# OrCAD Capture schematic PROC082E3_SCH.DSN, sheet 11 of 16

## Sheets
11 15. POWER: size C; title: POWER
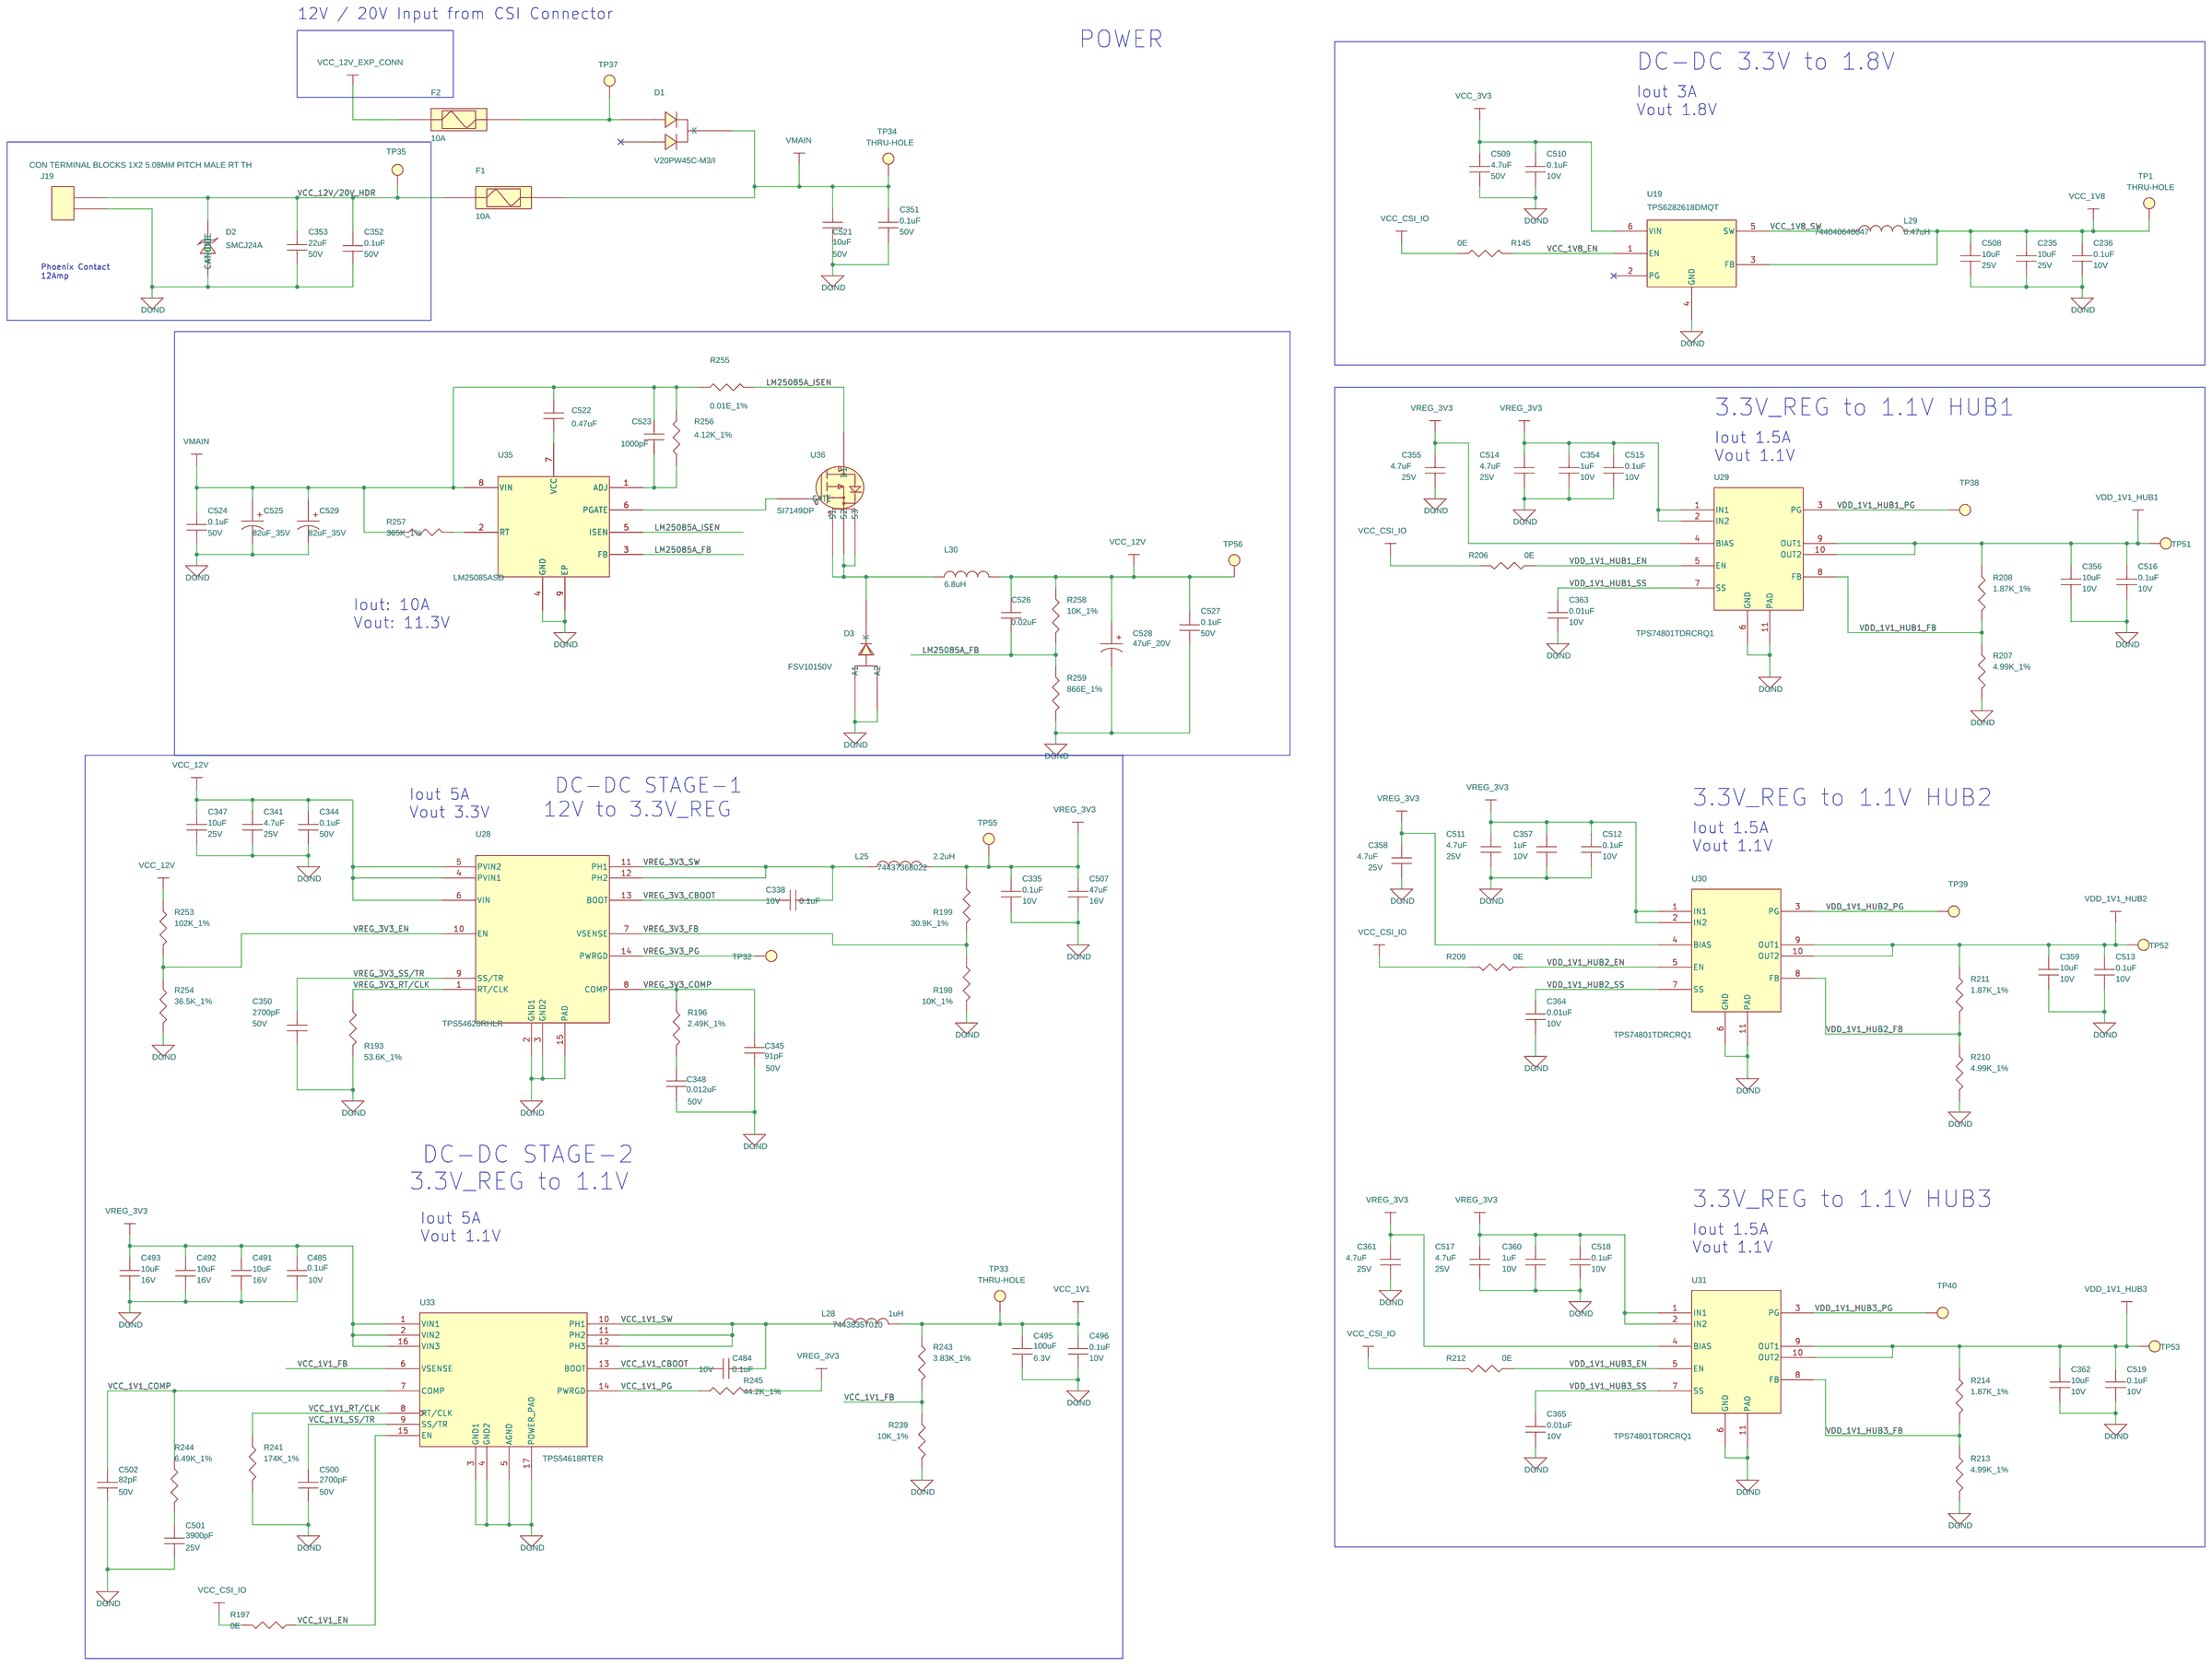
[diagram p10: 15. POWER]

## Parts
C235  10uF  [CAP0603_1]
C236  0.1uF  [CAP0402_0-75]
C335  0.1uF  [CAP0402_0-75]
C338  0.1uF  [CAP0402_0-75]
C341  4.7uF  [CAP0805_1-5]
C344  0.1uF  [CAP0402_0-75]
C345  91pF  [CAP0402_0-75]
C347  10uF  [CAP0603_1]
C348  0.012uF  [CAP0402_0-75]
C350  2700pF  [CAP0402_0-75]
C351  0.1uF  [CAP0402_0-75]
C352  0.1uF  [CAP0402_0-75]
C353  22uF  [CAP2220_5-5]
C354  1uF  [CAP0402_0-75]
C355  4.7uF  [CAP0805_1-5]
C356  10uF  [CAP0402_0-75]
C357  1uF  [CAP0402_0-75]
C358  4.7uF  [CAP0805_1-5]
C359  10uF  [CAP0402_0-75]
C360  1uF  [CAP0402_0-75]
C361  4.7uF  [CAP0805_1-5]
C362  10uF  [CAP0402_0-75]
C363  0.01uF  [CAP0201_0-5]
C364  0.01uF  [CAP0201_0-5]
C365  0.01uF  [CAP0201_0-5]
C484  0.1uF  [CAP0402_0-75]
C485  0.1uF  [CAP0402_0-75]
C491  10uF  [CAP0603_1]
C492  10uF  [CAP0603_1]
C493  10uF  [CAP0603_1]
C495  100uF  [CAP1206_2]
C496  0.1uF  [CAP0402_0-75]
C500  2700pF  [CAP0402_0-75]
C501  3900pF  [CAP0402_0-75]
C502  82pF  [CAP0402_0-75]
C507  47uF  [CAP1210_2-75]
C508  10uF  [CAP0603_1]
C509  4.7uF  [CAP1206_2]
C510  0.1uF  [CAP0402_0-75]
C511  4.7uF  [CAP0805_1-5]
C512  0.1uF  [CAP0402_0-75]
C513  0.1uF  [CAP0402_0-75]
C514  4.7uF  [CAP0805_1-5]
C515  0.1uF  [CAP0402_0-75]
C516  0.1uF  [CAP0402_0-75]
C517  4.7uF  [CAP0805_1-5]
C518  0.1uF  [CAP0402_0-75]
C519  0.1uF  [CAP0402_0-75]
C521  10uF  [CAP1206_2]
C522  0.47uF  [CAP0402_0-75]
C523  1000pF  [CAP0402_0-75]
C524  0.1uF  [CAP0402_0-75]
C525  82uF_35V  [CAPAE_E12CASE_12]
C526  0.02uF  [CAP1206_1]
C527  0.1uF  [CAP0402_0-75]
C528  47uF_20V  [CAPT6032C_3]
C529  82uF_35V  [CAPAE_E12CASE_12]
D1  V20PW45C-M3/I  [TO-252AE-3_V20PW45C_1-6]
D2  SMCJ24A  [DIO_SMC_2-7]
D3  FSV10150V  [TO277-3_FSV10150V_1-2]
F1  10A  [FUSEH_154004_380X200_SMD_3-9]
F2  10A  [FUSEH_154004_380X200_SMD_3-9]
J19  CON_TRBLK_1X2  [CON_TB1X2_1757242_P_R_T_8-6]
L25  2.2uH  [IND_74437368022_410X410_SMD_4]
L28  1uH  [IND_74438357010_170X170_SMD_3-1]
L29  0.47uH  [IND_744040640047_250X250_SMD_4-5]
L30  6.8uH  [IND_XAL1010_460X410_SMD]
R145  0E  [RES0402_0-5]
R193  53.6K_1%  [RES0402_0-5]
R196  2.49K_1%  [RES0402_0-5]
R197  0E  [RES0402_0-5]
R198  10K_1%  [RES0402_0-5]
R199  30.9K_1%  [RES0402_0-5]
R206  0E  [RES0402_0-5]
R207  4.99K_1%  [RES0402_0-5]
R208  1.87K_1%  [RES0402_0-5]
R209  0E  [RES0402_0-5]
R210  4.99K_1%  [RES0402_0-5]
R211  1.87K_1%  [RES0402_0-5]
R212  0E  [RES0402_0-5]
R213  4.99K_1%  [RES0402_0-5]
R214  1.87K_1%  [RES0402_0-5]
R239  10K_1%  [RES0402_0-5]
R241  174K_1%  [RES0402_0-5]
R243  3.83K_1%  [RES0402_0-5]
R244  6.49K_1%  [RES0402_0-5]
R245  44.2K_1%  [RES0402_0-5]
R253  102K_1%  [RES0402_0-5]
R254  36.5K_1%  [RES0402_0-5]
R255  0.01E_1%  [RES1206_0-75]
R256  4.12K_1%  [RES0402_0-5]
R257  365K_1%  [RES0402_0-5]
R258  10K_1%  [RES0201_0-5]
R259  866E_1%  [RES0402_0-5]
TP1  THRU HOLE  [TP_40X65]
TP32  TP40_SMD  [TP40_SMD]
TP33  THRU HOLE  [TP_40X65]
TP34  THRU HOLE  [TP_40X65]
TP35  TP40_SMD  [TP40_SMD]
TP37  TP40_SMD  [TP40_SMD]
TP38  TP30_SMD  [TP30_SMD]
TP39  TP30_SMD  [TP30_SMD]
TP40  TP30_SMD  [TP30_SMD]
TP51  TP40_SMD  [TP40_SMD]
TP52  TP40_SMD  [TP40_SMD]
TP53  TP40_SMD  [TP40_SMD]
TP55  TP40_SMD  [TP40_SMD]
TP56  TP40_SMD  [TP40_SMD]
U19  TPS6282618DMQT  [VSONHR6_TPS62826_60X60_1]
U28  TPS54620RHLR  [QFN14_19-68_145X145]
U29  TPS74801TDRCRQ1  [VSON10_TPS74801-Q1_120X120_1]
U30  TPS74801TDRCRQ1  [VSON10_TPS74801-Q1_120X120_1]
U31  TPS74801TDRCRQ1  [VSON10_TPS74801-Q1_120X120_1]
U33  TPS54618RTER  [QFN16_19-68_120X120_0-8_EP1-8]
U35  LM25085ASD  [DFN8_19-68_120X120_0-8_EP1-7X2-1]
U36  SI7149DP  [POWERPAKSO8_SI7848BDP_240X200_1-2]

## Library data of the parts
C235 C508 = CAP: CAP CERAMIC 10uF 25V 20% X5R 0603; Chkd/date: MANIRAJA/130617; Crtd /date: MUDDU/130810; Custom_Duty: 15%; Customs_HS_Code: 85322990; Distributor_name: DIGIKEY; Distributor_part_number: 490-7202-1-ND; Footprint Path: Y:\MIS_DATABASE\Library\ALTIUM_TOOL\PCB_FOOTPRINTS\Altium_Footprint_Lib.PcbLib; Height: 0.90MM; Library Path: Y:\MIS_DATABASE\Library\ALTIUM_TOOL\SCHEMATICS_PARTS\MS_DISCRETE_Library.schlib; Mfr_name: MURATA; Mfr_part_number: GRM188R61E106MA73D; Mistral Part No: 120013060015-R; Package: 0603; Part_type: CAPACITORS\CERAMIC; Project: PB_BUGBASE; RoHS: RoHS; Temperature: -55°C+85°C; Tolerance: 20%; Voltage: 25V; Wattage: NA; Weight: 6.3mg; Datasheet: Y:\MIS_DATABASE\DATASHEETS\CAPACITORS\MURATA-GXX-SER_NOV17.PDF
C236 C335 C338 C484 C485 C496 C510 C512 C513 C515 C516 C518 C519 = CAP: CAP CERAMIC 0.1uF 10V 10% X7R 0402; Automotive Alternate_mfr_name: TDK; Automotive Alternate_mfr_part_number: CGA2B1X7R1C104K050BC; Chkd/date: MANIRAJA/190218; Crtd /date: ALVY/160218; Custom_Duty: 15%; Customs_HS_Code: 85322990; Direct Alternate_mfr_name: TDK; Direct Alternate_mfr_part_number: CGA2B1X7R1C104K050BC; Distributor_name: DIGIKEY; Distributor_part_number: 490-6321-1-ND; Footprint Path: Y:\MIS_DATABASE\Library\ALTIUM_TOOL\PCB_FOOTPRINTS\Altium_Footprint_Lib.PcbLib; Height: 0.55MM; Library Path: Y:\MIS_DATABASE\Library\ALTIUM_TOOL\SCHEMATICS_PARTS\MS_DISCRETE_Library.schlib; Mfr_name: MURATA; Mfr_part_number: GRM155R71A104KA01D; Mistral Part No: 120018020011-R; Package: 0402; Part_type: CAPACITORS\CERAMIC; Project: GRACO SMART MODULE; RoHS: RoHS; Temperature: -55°C+125°C; Tolerance: 10%; Voltage: 10V; Wattage: NA; Weight: 6mg; Datasheet: Y:\MIS_DATABASE\DATASHEETS\CAPACITORS\GRM155R71A104KA01D.PDF
C341 = CAP: CAP CERAMIC 4.7uF 25V 10% X7R 0805; Chkd/date: MANIRAJA/301120; Crtd /date: ALVY/301120; Custom_Duty: 15%; Customs_HS_Code: 85322990; Distributor_name: MOUSER; Distributor_part_number: 81-GRM21BZ71E475KE5L; Footprint Path: Y:\MIS_DATABASE\Library\ALTIUM_TOOL\PCB_FOOTPRINTS\Altium_Footprint_Lib.PcbLib; Height: 1.45MM; Library Path: Y:\MIS_DATABASE\Library\ALTIUM_TOOL\SCHEMATICS_PARTS\MS_DISCRETE_Library.schlib; Mfr_name: MURATA; Mfr_part_number: GRM21BZ71E475KE15L; Mistral Part No: 120014060005-R; Package: 0805; Part_type: CAPACITORS\CERAMIC; Project: TI_J7ES_EVM_FUSION2_SER_CAP; RoHS: RoHS; Temperature: -55°C+125°C; Tolerance: 10%; Voltage: 25V; Wattage: NA; Weight: 1.6mg; Datasheet: Y:\MIS_DATABASE\DATASHEETS\CAPACITORS\GRM21BZ71E475KE15.PDF
C344 C351 C352 C524 C527 = CAP: CAP CERAMIC 0.1uF 50V 10% X7R 0402; Chkd/date: MANIRAJA/131217; Crtd /date: ALVY/131217; Custom_Duty: 15%; Customs_HS_Code: 85322990; Distributor_name: DIGIKEY; Distributor_part_number: 478-10043-1-ND; Footprint Path: Y:\MIS_DATABASE\Library\ALTIUM_TOOL\PCB_FOOTPRINTS\Altium_Footprint_Lib.PcbLib; Height: 0.56MM; Library Path: Y:\MIS_DATABASE\Library\ALTIUM_TOOL\SCHEMATICS_PARTS\MS_DISCRETE_Library.schlib; Mfr_name: AVX CORPORATION; Mfr_part_number: 04025C104KAT2A; Mistral Part No: 120011100014-R; Package: 0402; Part_type: CAPACITORS\CERAMIC; Project: ASL_LIU_TYPE-II; RoHS: RoHS; Temperature: -55°C+125°C; Tolerance: 10%; Voltage: 50V; Wattage: NA; Weight: 0.65mg; Datasheet: Y:\MIS_DATABASE\DATASHEETS\CAPACITORS\AVX_MLC.PDF
C345 = CAP: CAP CERAMIC 91pF 50V 5% C0G(NP0) 0402; Chkd/date: VASANTHA/100215; Crtd /date: USMAN/170513; Custom_Duty: 15%; Customs_HS_Code: 85322990; Distributor_name: DIGIKEY; Distributor_part_number: 490-5954-1-ND; Footprint Path: Y:\MIS_DATABASE\Library\ALTIUM_TOOL\PCB_FOOTPRINTS\Altium_Footprint_Lib.PcbLib; Height: 0.55MM; Library Path: Y:\MIS_DATABASE\Library\ALTIUM_TOOL\SCHEMATICS_PARTS\MS_DISCRETE_Library.schlib; Mfr_name: MURATA; Mfr_part_number: GRM1555C1H910JA01D; Mistral Part No: 120013050007-R; Package: 0402; Part_type: CAPACITORS\CERAMIC; Project: DTRM; RoHS: RoHS; Temperature: -55°C+125°C; Tolerance: 5%; Voltage: 50V; Wattage: NA; Weight: 6mg; Datasheet: Y:\MIS_DATABASE\DATASHEETS\CAPACITORS\MURATA-GXX-SER_NOV17.PDF
C347 = CAP: CAP CERAMIC 10uF 25V 20% X5R 0603; Automotive Alternate_mfr_name: MURATA; Automotive Alternate_mfr_part_number: GRT188R61E106ME13D; Chkd/date: MANIRAJA/130617; Crtd /date: MUDDU/130810; Custom_Duty: 15%; Customs_HS_Code: 85322990; Direct Alternate_mfr_name: TDK; Direct Alternate_mfr_part_number: C1608X5R1E106M080AC; Distributor_name: DIGIKEY; Distributor_part_number: 490-7202-1-ND; Footprint Path: Y:\MIS_DATABASE\Library\ALTIUM_TOOL\PCB_FOOTPRINTS\Altium_Footprint_Lib.PcbLib; Height: 0.90MM; Library Path: Y:\MIS_DATABASE\Library\ALTIUM_TOOL\SCHEMATICS_PARTS\MS_DISCRETE_Library.schlib; Mfr_name: MURATA; Mfr_part_number: GRM188R61E106MA73D; Mistral Part No: 120013060015-R; Package: 0603; Part_type: CAPACITORS\CERAMIC; Project: PB_BUGBASE; RoHS: RoHS; Temperature: -55°C+85°C; Tolerance: 20%; Voltage: 25V; Wattage: NA; Weight: 6.3mg; Datasheet: Y:\MIS_DATABASE\DATASHEETS\CAPACITORS\MURATA-GXX-SER_NOV17.PDF
C348 = CAP: CAP CERAMIC 0.012uF 50V 10% X7R 0402; Chkd/date: MANIRAJA/140219; Crtd /date: ALVY/140219; Custom_Duty: 15%; Customs_HS_Code: 85322990; Distributor_name: DIGIKEY; Distributor_part_number: 1292-1182-1-ND; Footprint Path: Y:\MIS_DATABASE\Library\ALTIUM_TOOL\PCB_FOOTPRINTS\Altium_Footprint_Lib.PcbLib; Height: 0.70MM; Library Path: Y:\MIS_DATABASE\Library\ALTIUM_TOOL\SCHEMATICS_PARTS\MS_DISCRETE_Library.schlib; Mfr_name: WALSIN TECHNOLOGY; Mfr_part_number: 0402B123K500CT; Mistral Part No: 120019020007-R; Package: 0402; Part_type: CAPACITORS\CERAMIC; Project: GRACO SMART MODULE; RoHS: RoHS; Temperature: -55°C+125°C; Tolerance: 10%; Voltage: 50V; Wattage: NA; Weight: NA; Datasheet: Y:\MIS_DATABASE\DATASHEETS\CAPACITORS\0402B123K500CT.PDF
C350 C500 = CAP: CAP CERAMIC 2700pF 50V 10% X7R 0402; Chkd/date: VASANTHA/201216; Crtd /date: CHAITHANYA/071111; Custom_Duty: 15%; Customs_HS_Code: 85322990; Distributor_name: DIGIKEY; Distributor_part_number: 490-1306-1-ND; Footprint Path: Y:\MIS_DATABASE\Library\ALTIUM_TOOL\PCB_FOOTPRINTS\Altium_Footprint_Lib.PcbLib; Height: 0.55MM; Library Path: Y:\MIS_DATABASE\Library\ALTIUM_TOOL\SCHEMATICS_PARTS\MS_DISCRETE_Library.schlib; Mfr_name: MURATA; Mfr_part_number: GRM155R71H272KA01D; Mistral Part No: 120011110004-R; Package: 0402; Part_type: CAPACITORS\CERAMIC; Project: DLRL_FPGA_DEV_PF; RoHS: RoHS; Temperature: -55°C+125°C; Tolerance: 10%; Voltage: 50V; Wattage: NA; Weight: 6mg; Datasheet: Y:\MIS_DATABASE\DATASHEETS\CAPACITORS\GRM155R71H272KA01.PDF
C353 = CAP: CAP CERAMIC 22uF 50V 20% X5R 2220; Chkd/date: BAVISH/081111; Crtd /date: CHAITHANYA/211011; Custom_Duty: 15%; Customs_HS_Code: 85322990; Distributor_name: DIGIKEY; Distributor_part_number: 445-1655-1-ND; Footprint Path: Y:\MIS_DATABASE\Library\ALTIUM_TOOL\PCB_FOOTPRINTS\Altium_Footprint_Lib.PcbLib; Height: 5.50MM; Library Path: Y:\MIS_DATABASE\Library\ALTIUM_TOOL\SCHEMATICS_PARTS\MS_DISCRETE_Library.schlib; Mfr_name: TDK CORPORATION; Mfr_part_number: CKG57NX5R1H226M500JH; Mistral Part No: 120011100042-R; Package: 2220; Part_type: CAPACITORS\CERAMIC; Project: NA10NG; RoHS: RoHS; Temperature: -55°C+85°C; Tolerance: 20%; Voltage: 50V; Wattage: NA; Weight: NA; Datasheet: Y:\MIS_DATABASE\DATASHEETS\CAPACITORS\CKG57NX5R1H226M500JH.PDF
C354 C357 C360 = CAP: CAP CERAMIC 1uF 10V 10% X7S AUTO 0402; Chkd/date: MANIRAJA/100918; Crtd /date: ALVY/100918; Custom_Duty: 15%; Customs_HS_Code: 85322990; Distributor_name: DIGIKEY; Distributor_part_number: 490-13409-1-ND; Footprint Path: Y:\MIS_DATABASE\Library\ALTIUM_TOOL\PCB_FOOTPRINTS\Altium_Footprint_Lib.PcbLib; Footprint Ref: CAP0402_0-5; Height: 0.70MM; Library Path: Y:\MIS_DATABASE\Library\ALTIUM_TOOL\SCHEMATICS_PARTS\MS_DISCRETE_Library.schlib; Mfr_name: MURATA; Mfr_part_number: GCM155C71A105KE38D; Mistral Part No: 120018090021-R; Package: 0402; Part_type: CAPACITORS\CERAMIC; Project: SMART-M_SCRIPTALK_PB; RoHS: RoHS; Temperature: -55°C+125°C; Tolerance: 10%; Voltage: 10V; Wattage: NA; Weight: 6mg; Datasheet: Y:\MIS_DATABASE\DATASHEETS\CAPACITORS\MURATA-GCM-SER.PDF
C355 C358 C361 C511 C514 C517 = CAP: CAP CERAMIC 4.7uF 25V 10% X5R 0805; Chkd/date: MANIRAJA/100419; Crtd /date: ALVY/100419; Custom_Duty: 15%; Customs_HS_Code: 85322990; Distributor_name: DIGIKEY; Distributor_part_number: 399-5505-1-ND; Footprint Path: Y:\MIS_DATABASE\Library\ALTIUM_TOOL\PCB_FOOTPRINTS\Altium_Footprint_Lib.PcbLib; Height: 1.40MM; Library Path: Y:\MIS_DATABASE\Library\ALTIUM_TOOL\SCHEMATICS_PARTS\MS_DISCRETE_Library.schlib; Mfr_name: KEMET; Mfr_part_number: C0805C475K3PACTU; Mistral Part No: 120011020009-R; Package: 0805; Part_type: CAPACITORS\CERAMIC; Project: S-BAND_TM-2W_PS; RoHS: RoHS; Temperature: -55°C+85°C; Tolerance: 10%; Voltage: 25V; Wattage: NA; Weight: 5.5mg; Datasheet: Y:\MIS_DATABASE\DATASHEETS\CAPACITORS\KEMET-C-X5R.PDF
C356 C359 C362 = CAP: CAP CERAMIC 10uF 10V 20% X5R 0402; Chkd/date: VASANTHA/291216; Crtd /date: USMAN/261113; Custom_Duty: 15%; Customs_HS_Code: 85322990; Distributor_name: DIGIKEY; Distributor_part_number: 1276-1450-1-ND; Footprint Path: Y:\MIS_DATABASE\Library\ALTIUM_TOOL\PCB_FOOTPRINTS\Altium_Footprint_Lib.PcbLib; Height: 0.55MM; Library Path: Y:\MIS_DATABASE\Library\ALTIUM_TOOL\SCHEMATICS_PARTS\MS_DISCRETE_Library.schlib; Mfr_name: SAMSUNG; Mfr_part_number: CL05A106MP5NUNC; Mistral Part No: 120013110019-R; Package: 0402; Part_type: CAPACITORS\CERAMIC; Project: C-BAND_SYNTH; RoHS: RoHS; Temperature: -55°C+85°C; Tolerance: 20%; Voltage: 10V; Wattage: NA; Weight: 0.65mg; Datasheet: Y:\MIS_DATABASE\DATASHEETS\CAPACITORS\CL05A106MP5NUNC.PDF
C363-C365 = CAP: CAP CERAMIC 0.01uF 10V 10% X5R 0201; Chkd/date: VASANTHA/270117; Crtd /date: MAZHAR/090909; Custom_Duty: 15%; Customs_HS_Code: 85322990; Distributor_name: DIGIKEY; Distributor_part_number: 490-3166-1-ND; Footprint Path: Y:\MIS_DATABASE\Library\ALTIUM_TOOL\PCB_FOOTPRINTS\Altium_Footprint_Lib.PcbLib; Footprint Ref: CAP0402_0-75; Height: 0.33MM; Library Path: Y:\MIS_DATABASE\Library\ALTIUM_TOOL\SCHEMATICS_PARTS\MS_DISCRETE_Library.schlib; Mfr_name: MURATA; Mfr_part_number: GRM033R61A103KA01D; Mistral Part No: 120011010015-R; Package: 0201; Part_type: CAPACITORS\CERAMIC; Project: VMEFMCD; RoHS: RoHS; Temperature: -55°C+85°C; Tolerance: 10%; Voltage: 10V; Wattage: NA; Weight: 0.33mg; Datasheet: Y:\MIS_DATABASE\DATASHEETS\CAPACITORS\MURATA-GXX-SER_NOV17.PDF
C491-C493 = CAP: CAP CERAMIC 10uF 16V 20% X6S 0603; Chkd/date: VASANTHA/170117; Crtd /date: VASANTHA/170117; Custom_Duty: 15%; Customs_HS_Code: 85322990; Direct Alternate_mfr_name: SAMSUNG; Direct Alternate_mfr_part_number: CL10X106MO8NRNC; Distributor_name: DIGIKEY; Distributor_part_number: 490-7198-1-ND; Height: 0.90MM; Mfr_name: MURATA; Mfr_part_number: GRM188C81C106MA73D; Mistral Part No: 120017010004-R; Package: 0603; Part_type: CAPACITORS\CERAMIC; Project: TRMM_SMART-M_PS; RoHS: RoHS; Temperature: -55°C+105°C; Tolerance: 20%; Voltage: 16V; Wattage: NA; Weight: 6.3mg; Datasheet: Y:\MIS_DATABASE\DATASHEETS\CAPACITORS\MURATA-GXX-SER_NOV17.PDF
C495 = CAP: CAP CERAMIC 100uF 6.3V 20% X5R 1206; Chkd/date: MANIRAJA/010419; Crtd /date: MANIRAJA/010419; Custom_Duty: 15%; Customs_HS_Code: 85322990; Distributor_name: DIGIKEY; Distributor_part_number: 490-7217-1-ND; Height: 1.90MM; Mfr_name: MURATA; Mfr_part_number: GRM31CR60J107ME39K; Mistral Part No: 120009030174-R; Package: 1206; Part_type: CAPACITORS\CERAMIC; Project: HS100RD; RoHS: RoHS; Temperature: -55°C+85°C; Tolerance: 20%; Voltage: 6.3V; Wattage: NA; Weight: 16.2mg; Datasheet: Y:\MIS_DATABASE\DATASHEETS\CAPACITORS\GRM31CR60J107ME39.PDF
C501 = CAP: CAP CERAMIC 3900pF 25V 5% X7R 0402; Chkd/date: MANIRAJA/061218; Crtd /date: ALVY/061218; Custom_Duty: 15%; Customs_HS_Code: 85322990; Distributor_name: DIGIKEY; Distributor_part_number: 478-11747-1-ND; Footprint Path: Y:\MIS_DATABASE\Library\ALTIUM_TOOL\PCB_FOOTPRINTS\Altium_Footprint_Lib.PcbLib; Height: 0.56MM; Library Path: Y:\MIS_DATABASE\Library\ALTIUM_TOOL\SCHEMATICS_PARTS\MS_DISCRETE_Library.schlib; Mfr_name: AVX CORPORATION; Mfr_part_number: 04023C392JAT2A; Mistral Part No: 120018120005-R; Package: 0402; Part_type: CAPACITORS\CERAMIC; Project: RFSU_POC-CARD; RoHS: RoHS; Temperature: -55°C+125°C; Tolerance: 5%; Voltage: 25V; Wattage: NA; Weight: 0.65mg; Datasheet: Y:\MIS_DATABASE\DATASHEETS\CAPACITORS\AVX_MLC.PDF
C502 = CAP: CAP CERAMIC 82pF 50V 2% C0G(NP0) 0402; Chkd/date: MANIRAJA/040620; Crtd /date: ALVY/040620; Custom_Duty: 15%; Customs_HS_Code: 85322990; Distributor_name: DIGIKEY; Distributor_part_number: 490-8229-1-ND; Footprint Path: Y:\MIS_DATABASE\Library\ALTIUM_TOOL\PCB_FOOTPRINTS\Altium_Footprint_Lib.PcbLib; Height: 0.55MM; Library Path: Y:\MIS_DATABASE\Library\ALTIUM_TOOL\SCHEMATICS_PARTS\MS_DISCRETE_Library.schlib; Mfr_name: MURATA; Mfr_part_number: GRM1555C1H820GA01D; Mistral Part No: 120020060013-R; Package: 0402; Part_type: CAPACITORS\CERAMIC; Project: MCX_80MHz_ADC_DRIVER; RoHS: RoHS; Temperature: -55°C+125°C; Tolerance: 2%; Voltage: 50V; Wattage: NA; Weight: 6mg; Datasheet: Y:\MIS_DATABASE\DATASHEETS\CAPACITORS\GRM1555C1H820GA01.PDF
C507 = CAP: CAP CERAMIC 47uF 16V 10% X6S AUTO 1210; Chkd/date: MANIRAJA/270218; Crtd /date: ALVY/260218; Custom_Duty: 15%; Customs_HS_Code: 85322990; Distributor_name: DIGIKEY; Distributor_part_number: 490-12494-1-ND; Footprint Path: Y:\MIS_DATABASE\Library\ALTIUM_TOOL\PCB_FOOTPRINTS\Altium_Footprint_Lib.PcbLib; Height: 2.70MM; Library Path: Y:\MIS_DATABASE\Library\ALTIUM_TOOL\SCHEMATICS_PARTS\MS_DISCRETE_Library.schlib; Mfr_name: MURATA; Mfr_part_number: GRT32EC81C476KE13L; Mistral Part No: 120018020017-R; Package: 1210; Part_type: CAPACITORS\CERAMIC; Project: RSAPR_TYPE-II_DIO; RoHS: RoHS; Temperature: -55°C+105°C; Tolerance: 10%; Voltage: 16V; Wattage: NA; Weight: 16mg; Datasheet: Y:\MIS_DATABASE\DATASHEETS\CAPACITORS\GRT32EC81C476KE13.PDF
C509 = CAP: CAP CERAMIC 4.7uF 50V 10% X7R 1206; Chkd/date: VASANTHA/100315; Crtd /date: NAVEED/240714; Custom_Duty: 15%; Customs_HS_Code: 85322990; Distributor_name: DIGIKEY; Distributor_part_number: 587-2994-1-ND; Footprint Path: Y:\MIS_DATABASE\Library\ALTIUM_TOOL\PCB_FOOTPRINTS\Altium_Footprint_Lib.PcbLib; Height: 1.80MM; Library Path: Y:\MIS_DATABASE\Library\ALTIUM_TOOL\SCHEMATICS_PARTS\MS_DISCRETE_Library.schlib; Mfr_name: TAIYO YUDEN; Mfr_part_number: UMK316AB7475KL-T; Mistral Part No: 120014070019-R; Package: 1206; Part_type: CAPACITORS\CERAMIC; Project: MS_ADE_PSM_PSU; RoHS: RoHS; Temperature: -55°C+125°C; Tolerance: 10%; Voltage: 50V; Wattage: NA; Weight: 16.2mg; Datasheet: Y:\MIS_DATABASE\DATASHEETS\CAPACITORS\UMK316AB7475KL-T.PDF
C521 = CAP: CAP CERAMIC 10uF 50V 10% X5R AUTO 1206; Chkd/date: MANIRAJA/261018; Crtd /date: ALVY/261018; Custom_Duty: 15%; Customs_HS_Code: 85322990; Distributor_name: DIGIKEY; Distributor_part_number: 490-12456-1-ND; Footprint Path: Y:\MIS_DATABASE\Library\ALTIUM_TOOL\PCB_FOOTPRINTS\Altium_Footprint_Lib.PcbLib; Height: 1.80MM; Library Path: Y:\MIS_DATABASE\Library\ALTIUM_TOOL\SCHEMATICS_PARTS\MS_DISCRETE_Library.schlib; Mfr_name: MURATA; Mfr_part_number: GRT31CR61H106KE01L; Mistral Part No: 120011060019-R; Package: 1206; Part_type: CAPACITORS\CERAMIC; Project: LRDE_ABCMV2_MB; RoHS: RoHS; Temperature: -55°C+85°C; Tolerance: 10%; Voltage: 50V; Wattage: NA; Weight: 16.2mg; Datasheet: Y:\MIS_DATABASE\DATASHEETS\CAPACITORS\GRT31CR61H106KE01L.PDF
C522 = CAP: CAP CERAMIC 0.47uF 50V 10% X5R 0402; Chkd/date: MANIRAJA/250821; Crtd /date: ALVY/250821; Custom_Duty: 15%; Customs_HS_Code: 85322990; Distributor_name: DIGIKEY; Distributor_part_number: 490-16354-1-ND; Footprint Path: Y:\MIS_DATABASE\Library\ALTIUM_TOOL\PCB_FOOTPRINTS\Altium_Footprint_Lib.PcbLib; Height: 0.60MM; Library Path: Y:\MIS_DATABASE\Library\ALTIUM_TOOL\SCHEMATICS_PARTS\MS_DISCRETE_Library.schlib; Mfr_name: MURATA; Mfr_part_number: GRM155R61H474KE11D; Mistral Part No: 120019050024-R; Package: 0402; Part_type: CAPACITORS\CERAMIC; Project: TI_AM335x SK_BRD; RoHS: RoHS; Temperature: -55°C+85°C; Tolerance: 10%; Voltage: 50V; Wattage: NA; Weight: 1.5mg; Datasheet: Y:\MIS_DATABASE\DATASHEETS\CAPACITORS\GRM155R61H474KE11.PDF
C523 = CAP: CAP CERAMIC 1000pF 50V 5% X7R 0402; Chkd/date: MANIRAJA/010419; Crtd /date: MANIRAJA/010419; Custom_Duty: 15%; Customs_HS_Code: 85322990; Distributor_name: DIGIKEY; Distributor_part_number: 490-6349-1-ND; Footprint Path: Y:\MIS_DATABASE\Library\ALTIUM_TOOL\PCB_FOOTPRINTS\Altium_Footprint_Lib.PcbLib; Height: 0.55MM; Library Path: Y:\MIS_DATABASE\Library\ALTIUM_TOOL\SCHEMATICS_PARTS\MS_DISCRETE_Library.schlib; Mfr_name: MURATA; Mfr_part_number: GRM155R71H102JA01J; Mistral Part No: 120013100001-R; Package: 0402; Part_type: CAPACITORS\CERAMIC; Project: C-BAND_SYNTH; RoHS: RoHS; Temperature: -55°C+125°C; Tolerance: 5%; Voltage: 50V; Wattage: NA; Weight: 6mg; Datasheet: Y:\MIS_DATABASE\DATASHEETS\CAPACITORS\GRM155R71H102JA01J.PDF
C525 C529 = CAP_POL: CAP POLYMER 82uF 35V 20% E12CASE_8383; Chkd/date: JEBRAN/250416; Crtd /date: VASANTHA/210416; Custom_Duty: 15%; Customs_HS_Code: 85322990; Distributor_name: DIGIKEY; Distributor_part_number: P16562CT-ND; Footprint Path: Y:\MIS_DATABASE\Library\ALTIUM_TOOL\PCB_FOOTPRINTS\Altium_Footprint_Lib.PcbLib; Height: 12.00MM; Library Path: Y:\MIS_DATABASE\Library\ALTIUM_TOOL\SCHEMATICS_PARTS\MS_DISCRETE_Library.schlib; Mfr_name: PANASONIC-ECG; Mfr_part_number: 35SVPF82M; Mistral Part No: 120016040007-R; Package: E12CASE_8383; Part_type: CAPACITORS\POLYPROPYLENE; Project: RCI_DLS_CARD_PS; RoHS: RoHS; Temperature: -55°C+105°C; Tolerance: 20%; Voltage: 35V; Wattage: NA; Weight: NA; Datasheet: Y:\MIS_DATABASE\DATASHEETS\CAPACITORS\SVPF-SERIES.PDF
C526 = CAP: CAP CERAMIC 0.02uF 50V 5% C0G(NP0) 1206; Chkd/date: PRAVEEN/250822; Crtd /date: PRAVEEN/250822; Custom_Duty: 15%; Customs_HS_Code: 85322990; Distributor_name: DIGIKEY; Distributor_part_number: 490-1760-1-ND; Footprint Path: Y:\MIS_DATABASE\Library\ALTIUM_TOOL\PCB_FOOTPRINTS\Altium_Footprint_Lib.PcbLib; Height: 0.95MM; Library Path: Y:\MIS_DATABASE\Library\ALTIUM_TOOL\SCHEMATICS_PARTS\MS_DISCRETE_Library.schlib; Mfr_name: MURATA; Mfr_part_number: GRM3195C1H203JA01D; Mistral Part No: 120022080076-R; Package: 1206; Part_type: CAPACITORS\CERAMIC; Project: J7ES_EVM_FUSION2_BRD; RoHS: RoHS; Temperature: -55°C+125°C; Tolerance: 5%; Voltage: 50V; Wattage: NA; Weight: 19mg; Datasheet: Y:\MIS_DATABASE\DATASHEETS\CAPACITORS\GRM3195C1H203JA01D.PDF
C528 = CAP_POL: CAP TANTALUM 47uF 20V 20% ESR 0.5E C6032; Chkd/date: ALVY/290621; Crtd /date: MANIRAJA/290621; Custom_Duty: 15%; Customs_HS_Code: 85322990; Distributor_name: DIGIKEY; Distributor_part_number: 478-8904-1-ND; Footprint Path: Y:\MIS_DATABASE\Library\ALTIUM_TOOL\PCB_FOOTPRINTS\Altium_Footprint_Lib.PcbLib; Height: 2.80MM; Library Path: Y:\MIS_DATABASE\Library\ALTIUM_TOOL\SCHEMATICS_PARTS\MS_DISCRETE_Library.schlib; Mfr_name: AVX CORPORATION; Mfr_part_number: TAJC476M020RNJ; Mistral Part No: 120021060023-R; Package: C6032; Part_type: CAPACITORS\TANTALUM; Project: MSU_BRD; RoHS: RoHS; Temperature: -55°C+125°C; Tolerance: 20%; Voltage: 20V; Wattage: NA; Weight: 300mg; Datasheet: Y:\MIS_DATABASE\DATASHEETS\CAPACITORS\AVX-TAJ-SER_OCT20.PDF
D1 = DIODE_V20PW45C: DIODE SCHOTTKY TMBS RECTIFIER 45V 10A TO-252AE-3; Chkd/date: MANIRAJA/190419; Crtd /date: MANIRAJA/190419; Custom_Duty: 15%; Customs_HS_Code: 85412900; Distributor_name: DIGIKEY; Distributor_part_number: V20PW45C-M3/IGICT-ND; Footprint Path: Y:\MIS_DATABASE\Library\ALTIUM_TOOL\PCB_FOOTPRINTS\Altium_Footprint_Lib.PcbLib; Height: 1.60MM; Library Path: Y:\MIS_DATABASE\Library\ALTIUM_TOOL\SCHEMATICS_PARTS\MS_DISCRETE_Library.schlib; Mfr_name: VISHAY; Mistral Part No: 130019040014-R; Package: TO-252AE-3; Part_type: DIODE\SCHOTTKY; Project: TI_J7ES_EVM_FUSION2_SER_CAP; RoHS: RoHS; Temperature: -40°C+150°C; Tolerance: NA; Voltage: NA; Wattage: NA; Weight: NA; Datasheet: Y:\MIS_DATABASE\DATASHEETS\DISCRETES\DIODES\V20PW45C.PDF
D2 = DIODE_TVS: DIODE TVS UNIDIR 1500W 24V SMC; Chkd/date: VASANTHA/291216; Crtd /date: MANIRAJA/281216; Custom_Duty: 15%; Customs_HS_Code: 85412900; Distributor_name: DIGIKEY; Distributor_part_number: SMCJ24ALFCT-ND; Height: 2.65MM; Mfr_name: LITTELFULE; Mistral Part No: 130016120055-R; Package: SMC; Part_type: DIODE\TVS; Project: DARE_ODM; RoHS: RoHS; Temperature: -55°C+150°C; Tolerance: NA; Voltage: 24V; Wattage: 1500W; Weight: 300mg; Datasheet: Y:\MIS_DATABASE\DATASHEETS\DISCRETES\DIODES\SMCJ-FAIRCHILD.PDF
D3 = DIODE_SCHOTTKY_SS3P4L: DIODE SCHOTTKY RECTIFIER 150V 10A TO277-3; Chkd/date: MANIRAJA/280918; Crtd /date: ALVY/280918; Custom_Duty: 15%; Customs_HS_Code: 85412900; Distributor_name: DIGIKEY; Distributor_part_number: FSV10150VCT-ND; Footprint Path: Y:\MIS_DATABASE\Library\ALTIUM_TOOL\PCB_FOOTPRINTS\Altium_Footprint_Lib.PcbLib; Height: 1.20MM; Library Path: Y:\MIS_DATABASE\Library\ALTIUM_TOOL\SCHEMATICS_PARTS\MS_DISCRETE_Library.schlib; Mfr_name: ON SEMICONDUCTOR; Mistral Part No: 130018090055-R; Package: TO277-3; Part_type: DIODE\SCHOTTKY; Project: TI_J7ES_EVM_CP; RoHS: RoHS; Temperature: -55°C+150°C; Tolerance: NA; Voltage: 150V; Wattage: NA; Weight: 113.6mg; Datasheet: Y:\MIS_DATABASE\DATASHEETS\DISCRETES\DIODES\FSV10150V.PDF
F1 F2 = FUSE_HOLDER_0154: FUSE AND HOLDER BLOK 10A SMD; Chkd/date: MANIRAJA/120219; Crtd /date: MANIRAJA/120219; Custom_Duty: NA; Customs_HS_Code: NA; Distributor_name: DIGIKEY; Distributor_part_number: F1251CT-ND; Footprint Path: Y:\MIS_DATABASE\Library\ALTIUM_TOOL\PCB_FOOTPRINTS\Altium_Footprint_Lib.PcbLib; Height: 3.81MM; Library Path: Y:\MIS_DATABASE\Library\ALTIUM_TOOL\SCHEMATICS_PARTS\MS_DISCRETE_Library.schlib; Mfr_name: LITTLE FUSE; Mfr_part_number: 0154010.DR; Mistral Part No: 130019020003-R; Package: SMD; Part_type: FUSE; Project: TI_J7ES_EVM_CP; RoHS: RoHS; Temperature: -55°C+125°C; Tolerance: NA; Voltage: NA; Wattage: NA; Weight: NA; Datasheet: Y:\MIS_DATABASE\DATASHEETS\MISC\FUSE\0154X-SER.PDF
J19 = CON_TRBLK_2X1: CON TERMINAL BLOCKS 1X2 5.08MM PITCH MALE RT TH; Chkd/date: MANIRAJA/260218; Crtd /date: ALVY/260218; Custom_Duty: 24%; Customs_HS_Code: 85369090; Distributor_name: DIGIKEY; Distributor_part_number: 277-1106-ND; Footprint Path: Y:\MIS_DATABASE\Library\ALTIUM_TOOL\PCB_FOOTPRINTS\Altium_Footprint_Lib.PcbLib; Height: 8.60MM; Library Path: Y:\MIS_DATABASE\Library\ALTIUM_TOOL\SCHEMATICS_PARTS\MS_CONNECTOR_Library.schlib; Mfr_name: PH0ENIX; Mfr_part_number: 1757242; Mistral Part No: 150018020024-R; Package: THRU-HOLE; Part_type: CONNECTOR\TERMINAL BLOCK; Project: GRACO SMART MODULE; RoHS: RoHS; Temperature: NA; Tolerance: NA; Voltage: NA; Wattage: NA; Weight: 0.96g; Datasheet: Y:\MIS_DATABASE\DATASHEETS\CONNECTORS\1757242.PDF
L25 = INDUCTOR: IND POWER 2.2uH 10A 20% SMD; Chkd/date: MANIRAJA/121120; Crtd /date: ALVY/121120; Custom_Duty: 24%; Customs_HS_Code: 85437099; Distributor_name: DIGIKEY; Distributor_part_number: 732-3387-1-ND; Height: 4.00MM; Mfr_name: WURTH ELEKTRONIK; Mfr_part_number: 74437368022; Mistral Part No: 130020110036-R; Package: SMD; Project: TI_J7ES_EVM_FUSION2_SER_CAP; RoHS: RoHS; Temperature: -40°C+125°C; Tolerance: 20%; Voltage: NA; Wattage: NA; Weight: 2267mg; Datasheet: Y:\MIS_DATABASE\DATASHEETS\DISCRETES\INDUCTORS\74437368022.PDF
L28 = INDUCTOR: IND POWER 1uH 7.4A 20% SMD; Chkd/date: ALVY/041120; Crtd /date: ALVY/041120; Custom_Duty: 24%; Customs_HS_Code: 85369090; Distributor_name: DIGIKEY; Distributor_part_number: 732-11197-1-ND; Footprint Path: Y:\MIS_DATABASE\Library\ALTIUM_TOOL\PCB_FOOTPRINTS\Altium_Footprint_Lib.PcbLib; Height: 3.10MM; Library Path: Y:\MIS_DATABASE\Library\ALTIUM_TOOL\SCHEMATICS_PARTS\MS_DISCRETE_Library.schlib; Mfr_name: WURTH ELECTRONICS; Mfr_part_number: 74438357010; Mistral Part No: 130020110010-R; Package: SMD; Project: BRITESCAN; RoHS: RoHS; Temperature: -40°C+125°C; Tolerance: 20%; Voltage: NA; Wattage: NA; Weight: 340mg; Datasheet: Y:\MIS_DATABASE\DATASHEETS\DISCRETES\INDUCTORS\74438357010.PDF
L29 = INDUCTOR: IND POWER 0.47uH 8A 30% SMD; Chkd/date: MANIRAJA/280520; Crtd /date: ALVY/280520; Custom_Duty: 24%; Customs_HS_Code: 85437099; Distributor_name: DIGIKEY; Distributor_part_number: 732-7271-1-ND; Footprint Path: Y:\MIS_DATABASE\Library\ALTIUM_TOOL\PCB_FOOTPRINTS\Altium_Footprint_Lib.PcbLib; Height: 4.50MM; Library Path: Y:\MIS_DATABASE\Library\ALTIUM_TOOL\SCHEMATICS_PARTS\MS_DISCRETE_Library.schlib; Mfr_name: WURTH ELECTRONICS; Mfr_part_number: 744040640047; Mistral Part No: 130020050042-R; Package: SMD; Project: AM64x-GP_EVM BRD; RoHS: RoHS; Temperature: -40°C+125°C; Tolerance: 30%; Voltage: NA; Wattage: NA; Weight: 530mg; Datasheet: Y:\MIS_DATABASE\DATASHEETS\DISCRETES\INDUCTORS\744040640047.PDF
L30 = INDUCTOR: IND POWER 6.8uH 20% 18.5A SMD; Chkd/date: PRAVEEN/220822; Crtd /date: PRAVEEN/220822; Custom_Duty: 24%; Customs_HS_Code: 85437099; Distributor_name: MOUSER; Distributor_part_number: 994-XAL1010-682MEB; Footprint Path: Y:\MIS_DATABASE\Library\ALTIUM_TOOL\PCB_FOOTPRINTS\Altium_Footprint_Lib.PcbLib; Height: 10.00MM; Library Path: Y:\MIS_DATABASE\Library\ALTIUM_TOOL\SCHEMATICS_PARTS\MS_DISCRETE_Library.schlib; Mfr_name: COIL CRAFT; Mfr_part_number: XAL1010-682MEB; Mistral Part No: 130022080053-R; Package: SMD; Project: J7ES_EVM_FUSION2_BRD; RoHS: RoHS; Temperature: -40°C+125°C; Tolerance: 20%; Voltage: NA; Wattage: NA; Weight: 6.3g; Datasheet: Y:\MIS_DATABASE\DATASHEETS\DISCRETES\INDUCTORS\XAL1010XXX.PDF
R145 R197 R206 R209 R212 = RESISTOR: RES 0E 1/10W JUMPER 0402; Chkd/date: VASANTHA/061216; Crtd /date: NAVEED/201014; Custom_Duty: 15%; Customs_HS_Code: 85332119; Distributor_name: DIGIKEY; Distributor_part_number: P0.0JCT-ND; Footprint Path: Y:\MIS_DATABASE\Library\ALTIUM_TOOL\PCB_FOOTPRINTS\Altium_Footprint_Lib.PcbLib; Height: 0.40MM; IBISSP_MODLES: VALUE REPEATING 2 TIME; Library Path: Y:\MIS_DATABASE\Library\ALTIUM_TOOL\SCHEMATICS_PARTS\MS_DISCRETE_Library.schlib; Mfr_name: PANASONIC-ECG; Mfr_part_number: ERJ-2GE0R00X; Mistral Part No: 110018030052-R; Package: 0402; Part_type: RESISTORS\FIXED; Project: AEGIS POM; RoHS: RoHS; Temperature: -55°C+155°C; Tolerance: NA; Voltage: NA; Wattage: 1/10W; Weight: 0.8mg; Datasheet: Y:\MIS_DATABASE\DATASHEETS\RESISTORS\PAN-ERJSER_NOV17.PDF
R193 = RESISTOR: RES 53.6K 1/10W 1% 0402; Chkd/date: ALVY/020620; Crtd /date: MANIRAJA/020620; Custom_Duty: 15%; Customs_HS_Code: 85332119; Distributor_name: DIGIKEY; Distributor_part_number: 2019-RK73H1ETTP5362FCT-ND; Footprint Path: Y:\MIS_DATABASE\Library\ALTIUM_TOOL\PCB_FOOTPRINTS\Altium_Footprint_Lib.PcbLib; Height: 0.40MM; Library Path: Y:\MIS_DATABASE\Library\ALTIUM_TOOL\SCHEMATICS_PARTS\MS_DISCRETE_Library.schlib; Mfr_name: KOA SPEER; Mfr_part_number: RK73H1ETTP5362F; Mistral Part No: 110020060014-R; Package: 0402; Part_type: RESISTORS\FIXED; Project: 32CHSCC CONTROLLER CARD; RoHS: RoHS; Temperature: -55°C+155°C; Tolerance: 1%; Voltage: NA; Wattage: 1/10W; Weight: 0.65mg; Datasheet: Y:\MIS_DATABASE\DATASHEETS\RESISTORS\RK73H-SER.PDF
R196 = RESISTOR: RES 2.49K 1/16W 1% 0402; Chkd/date: VASANTHA/050115; Crtd /date: USMAN/300709; Custom_Duty: 15%; Customs_HS_Code: 85332119; Distributor_name: DIGIKEY; Distributor_part_number: 541-2.49KLCT-ND; Footprint Path: Y:\MIS_DATABASE\Library\ALTIUM_TOOL\PCB_FOOTPRINTS\Altium_Footprint_Lib.PcbLib; Height: 0.40MM; Library Path: Y:\MIS_DATABASE\Library\ALTIUM_TOOL\SCHEMATICS_PARTS\MS_DISCRETE_Library.schlib; Mfr_name: VISHAY; Mfr_part_number: CRCW04022K49FKED; Mistral Part No: 110016050020-R; Package: 0402; Part_type: RESISTORS\FIXED; Project: VMEFMCD; RoHS: RoHS; Temperature: -55°C+155°C; Tolerance: 1%; Voltage: NA; Wattage: 1/16W; Weight: 0.65mg; Datasheet: Y:\MIS_DATABASE\DATASHEETS\RESISTORS\CRCW0603.PDF
R198 R239 = RESISTOR: RES 10K 1/16W 1% 0402; Chkd/date: VASANTHA/201216; Crtd /date: GEETHA/290506; Custom_Duty: 15%; Customs_HS_Code: 85332119; Distributor_name: DIGIKEY; Distributor_part_number: 311-10.0KLRTR-ND; Footprint Path: Y:\MIS_DATABASE\Library\ALTIUM_TOOL\PCB_FOOTPRINTS\Altium_Footprint_Lib.PcbLib; Height: 0.40MM; Library Path: Y:\MIS_DATABASE\Library\ALTIUM_TOOL\SCHEMATICS_PARTS\MS_DISCRETE_Library.schlib; Mfr_name: YAGEO AMERICA; Mfr_part_number: RC0402FR-0710KL; Mistral Part No: 110015090015-R; Package: 0402; Part_type: RESISTORS\FIXED; Project: VOCERA; RoHS: RoHS; Temperature: -55°C+155°C; Tolerance: 1%; Voltage: NA; Wattage: 1/16W; Weight: 0.65mg; Datasheet: Y:\MIS_DATABASE\DATASHEETS\RESISTORS\RCXXXXL-SER_MAR18.PDF
R199 = RESISTOR: RES 30.9K 1/10W 1% 0402; Chkd/date: MAZHAR/080311; Crtd /date: BAVISH/230211; Custom_Duty: 15%; Customs_HS_Code: 85332119; Distributor_name: DIGIKEY; Distributor_part_number: P30.9KLCT-ND; Footprint Path: Y:\MIS_DATABASE\Library\ALTIUM_TOOL\PCB_FOOTPRINTS\Altium_Footprint_Lib.PcbLib; Height: 0.40MM; Library Path: Y:\MIS_DATABASE\Library\ALTIUM_TOOL\SCHEMATICS_PARTS\MS_DISCRETE_Library.schlib; Mfr_name: PANASONIC-ECG; Mfr_part_number: ERJ-2RKF3092X; Mistral Part No: 110011020022-R; Package: 0402; Part_type: RESISTORS\FIXED; Project: GOLDEN-I; RoHS: RoHS; Temperature: -55°C+155°C; Tolerance: 1%; Voltage: NA; Wattage: 1/10W; Weight: 0.8mg; Datasheet: Y:\MIS_DATABASE\DATASHEETS\RESISTORS\PAN-ERJSER_NOV17.PDF
R207 R210 R213 = RESISTOR: RES 4.99K 1/10W 1% 0402; Chkd/date: VASANTHA/281216; Crtd /date: MAZHAR/150506; Custom_Duty: 15%; Customs_HS_Code: 85332119; Distributor_name: DIGIKEY; Distributor_part_number: P4.99KLCT-ND; Footprint Path: Y:\MIS_DATABASE\Library\ALTIUM_TOOL\PCB_FOOTPRINTS\Altium_Footprint_Lib.PcbLib; Height: 0.40MM; Library Path: Y:\MIS_DATABASE\Library\ALTIUM_TOOL\SCHEMATICS_PARTS\MS_DISCRETE_Library.schlib; Mfr_name: PANASONIC-ECG; Mfr_part_number: ERJ-2RKF4991X; Mistral Part No: 110009030808-R; Package: 0402; Part_type: RESISTORS\FIXED; Project: VOCERA; RoHS: RoHS; Temperature: -55°C+155°C; Tolerance: 1%; Voltage: NA; Wattage: 1/10W; Weight: 0.8mg; Datasheet: Y:\MIS_DATABASE\DATASHEETS\RESISTORS\PAN-ERJSER_NOV17.PDF
R208 R211 R214 = RESISTOR: RES 1.87K 1/10W 1% 0402; Chkd/date: MAZHAR/151208; Crtd /date: USMAN/251108; Custom_Duty: 15%; Customs_HS_Code: 85332119; Distributor_name: DIGIKEY; Distributor_part_number: P1.87KLCT-ND; Footprint Path: Y:\MIS_DATABASE\Library\ALTIUM_TOOL\PCB_FOOTPRINTS\Altium_Footprint_Lib.PcbLib; Height: 0.40MM; Library Path: Y:\MIS_DATABASE\Library\ALTIUM_TOOL\SCHEMATICS_PARTS\MS_DISCRETE_Library.schlib; Mfr_name: PANASONIC-ECG; Mfr_part_number: ERJ-2RKF1871X; Mistral Part No: 110009030145-R; Package: 0402; Part_type: RESISTORS\FIXED; Project: KHAN_HSST; RoHS: RoHS; Temperature: -55°C+155°C; Tolerance: 1%; Voltage: NA; Wattage: 1/10W; Weight: 0.8mg; Datasheet: Y:\MIS_DATABASE\DATASHEETS\RESISTORS\PAN-ERJSER_NOV17.PDF
R241 = RESISTOR: RES 174K 1/16W 1% 0402; Chkd/date: MANIRAJA/040619; Crtd /date: ALVY/030619; Custom_Duty: 15%; Customs_HS_Code: 85332119; Distributor_name: DIGIKEY; Distributor_part_number: 541-174KLCT-ND; Height: 0.40MM; Mfr_name: VISHAY; Mfr_part_number: CRCW0402174KFKED; Mistral Part No: 110019040290-R; Package: 0402; Part_type: RESISTORS\FIXED; Project: MYTHIC_FORMFACTOR_BRD; RoHS: RoHS; Temperature: -55°C+155°C; Tolerance: 1%; Voltage: NA; Wattage: 1/16W; Weight: 0.65mg; Datasheet: Y:\MIS_DATABASE\DATASHEETS\RESISTORS\CRCW0603.PDF
R243 = RESISTOR: RES 3.83K 1/10W 1% 0402; Chkd/date: NAVEED/280515; Crtd /date: NAVEED/280515; Custom_Duty: 15%; Customs_HS_Code: 85332119; Distributor_name: DIGIKEY; Distributor_part_number: P3.83KLCT-ND; Footprint Path: Y:\MIS_DATABASE\Library\ALTIUM_TOOL\PCB_FOOTPRINTS\Altium_Footprint_Lib.PcbLib; Height: 0.40MM; Library Path: Y:\MIS_DATABASE\Library\ALTIUM_TOOL\SCHEMATICS_PARTS\MS_DISCRETE_Library.schlib; Mfr_name: PANASONIC-ECG; Mfr_part_number: ERJ-2RKF3831X; Mistral Part No: 110015050010-R; Package: 0402; Part_type: RESISTORS\FIXED; Project: DLRL NARROW BAND; RoHS: RoHS; Temperature: -55°C+155°C; Tolerance: 1%; Voltage: NA; Wattage: 1/10W; Weight: 0.8mg; Datasheet: Y:\MIS_DATABASE\DATASHEETS\RESISTORS\PAN-ERJSER_NOV17.PDF
R244 = RESISTOR: RES 6.49K 1/16W 1% 0402; Chkd/date: MANIRAJA/190718; Crtd /date: BAVISH/021210; Custom_Duty: 15%; Customs_HS_Code: 85332119; Distributor_name: DIGIKEY; Distributor_part_number: 541-6.49KLCT-ND; Height: 0.40MM; Mfr_name: VISHAY; Mfr_part_number: CRCW04026K49FKED; Mistral Part No: 110010120032-R; Package: 0402; Part_type: RESISTORS\FIXED; Project: TE4; RoHS: RoHS; Temperature: -55°C+155°C; Tolerance: 1%; Voltage: NA; Wattage: 1/16W; Weight: 0.65mg; Datasheet: Y:\MIS_DATABASE\DATASHEETS\RESISTORS\CRCW0603.PDF
R245 = RESISTOR: RES 44.2K 1/16W 1% 0402; Chkd/date: ALVY/041120; Crtd /date: ALVY/041120; Custom_Duty: 15%; Customs_HS_Code: 85332119; Distributor_name: DIGIKEY; Distributor_part_number: 541-4106-1-ND; Height: 0.35MM; Mfr_name: VISHAY; Mfr_part_number: CRCW040244K2FKEDC; Mistral Part No: 110010070032-R; Package: 0402; Part_type: RESISTORS\FIXED; Project: TI_J7ES_EVM_FUSION2_SER_CAP; RoHS: RoHS; Temperature: -55°C+155°C; Tolerance: 1%; Voltage: NA; Wattage: 1/16W; Weight: 0.65mg; Datasheet: Y:\MIS_DATABASE\DATASHEETS\RESISTORS\CRCW_C-SER.PDF
R253 = RESISTOR: RES 102K 1/16W 1% 0402; Chkd/date: MANIRAJA/160419; Crtd /date: ALVY/160419; Custom_Duty: 15%; Customs_HS_Code: 85332119; Distributor_name: DIGIKEY; Distributor_part_number: YAG2944CT-ND; Footprint Path: Y:\MIS_DATABASE\Library\ALTIUM_TOOL\PCB_FOOTPRINTS\Altium_Footprint_Lib.PcbLib; Height: 0.40MM; Library Path: Y:\MIS_DATABASE\Library\ALTIUM_TOOL\SCHEMATICS_PARTS\MS_DISCRETE_Library.schlib; Mfr_name: YAGEO AMERICA; Mfr_part_number: RC0402FR-07102KL; Mistral Part No: 110019040289-R; Package: 0402; Part_type: RESISTORS\FIXED; Project: TI_J7ES_EVM_FUSION2_SER_CAP; RoHS: RoHS; Temperature: -55°C+155°C; Tolerance: 1%; Voltage: NA; Wattage: 1/16W; Weight: 0.65mg; Datasheet: Y:\MIS_DATABASE\DATASHEETS\RESISTORS\RCXXXXL-SER_MAR18.PDF
R254 = RESISTOR: RES 36.5K 1/16W 1% 0402; Chkd/date: VASANTHA/291216; Crtd /date: USMAN/190508; Custom_Duty: 15%; Customs_HS_Code: 85332119; Distributor_name: DIGIKEY; Distributor_part_number: 541-36.5KLCT-ND; Footprint Path: Y:\MIS_DATABASE\Library\ALTIUM_TOOL\PCB_FOOTPRINTS\Altium_Footprint_Lib.PcbLib; Height: 0.40MM; Library Path: Y:\MIS_DATABASE\Library\ALTIUM_TOOL\SCHEMATICS_PARTS\MS_DISCRETE_Library.schlib; Mfr_name: VISHAY; Mfr_part_number: CRCW040236K5FKED; Mistral Part No: 110009030719-R; Package: 0402; Part_type: RESISTORS\FIXED; Project: KMB; RoHS: RoHS; Temperature: -55°C+155°C; Tolerance: 1%; Voltage: NA; Wattage: 1/16W; Weight: 0.65mg; Datasheet: Y:\MIS_DATABASE\DATASHEETS\RESISTORS\CRCW0603.PDF
R255 = RESISTOR: RES 0.01E 1/2W 1% 1206; Chkd/date: MANIRAJA/171018; Crtd /date: ALVY/171018; Custom_Duty: 15%; Customs_HS_Code: 85332119; Distributor_name: DIGIKEY; Distributor_part_number: CSR1206FK10L0CT-ND; Footprint Path: Y:\MIS_DATABASE\Library\ALTIUM_TOOL\PCB_FOOTPRINTS\Altium_Footprint_Lib.PcbLib; Height: 0.65MM; Library Path: Y:\MIS_DATABASE\Library\ALTIUM_TOOL\SCHEMATICS_PARTS\MS_DISCRETE_Library.schlib; Mfr_name: STACKPOLE ELECTRONICS; Mfr_part_number: CSR1206FK10L0; Mistral Part No: 110018100009-R; Package: 1206; Part_type: RESISTORS\FIXED; Project: TI_J7ES_EVM_CP; RoHS: RoHS; Temperature: -55°C+155°C; Tolerance: 1%; Voltage: NA; Wattage: 1/2W; Weight: NA; Datasheet: Y:\MIS_DATABASE\DATASHEETS\RESISTORS\CSR&CSRN-SER.PDF
R256 = RESISTOR: RES 4.12K 1/16W 1% 0402; Chkd/date: MANIRAJA/261020; Crtd /date: MANIRAJA/261020; Custom_Duty: 15%; Customs_HS_Code: 85332119; Distributor_name: DIGIKEY; Distributor_part_number: YAG3171CT-ND; Footprint Path: Y:\MIS_DATABASE\Library\ALTIUM_TOOL\PCB_FOOTPRINTS\Altium_Footprint_Lib.PcbLib; Height: 0.40MM; Library Path: Y:\MIS_DATABASE\Library\ALTIUM_TOOL\SCHEMATICS_PARTS\MS_DISCRETE_Library.schlib; Mfr_name: YAGEO AMERICA; Mfr_part_number: RC0402FR-074K12L; Mistral Part No: 110013110017-R; Package: 0402; Part_type: RESISTORS\FIXED; Project: TM2_1W_SEN10RO; RoHS: RoHS; Temperature: -55°C+155°C; Tolerance: 1%; Voltage: NA; Wattage: 1/16W; Weight: 0.65mg; Datasheet: Y:\MIS_DATABASE\DATASHEETS\RESISTORS\RCXXXXL-SER_MAR18.PDF
R257 = RESISTOR: RES 365K 1/10W 1% 0402; Chkd/date: MANIRAJA/290518; Crtd /date: MANIRAJA/150318; Custom_Duty: 15%; Customs_HS_Code: 85332119; Distributor_name: DIGIKEY; Distributor_part_number: P365KLCT-ND; Footprint Path: Y:\MIS_DATABASE\Library\ALTIUM_TOOL\PCB_FOOTPRINTS\Altium_Footprint_Lib.PcbLib; Height: 0.40MM; Library Path: Y:\MIS_DATABASE\Library\ALTIUM_TOOL\SCHEMATICS_PARTS\MS_DISCRETE_Library.schlib; Mfr_name: PANASONIC-ECG; Mfr_part_number: ERJ-2RKF3653X; Mistral Part No: 110018030010-R; Package: 0402; Part_type: RESISTORS\FIXED; Project: SD820_NANO_SOM; RoHS: RoHS; Temperature: -55°C+155°C; Tolerance: 1%; Voltage: NA; Wattage: 1/10W; Weight: 0.8mg; Datasheet: Y:\MIS_DATABASE\DATASHEETS\RESISTORS\PAN-ERJSER_NOV17.PDF
R258 = RESISTOR: RES 10K 1/20W 1% 0201; Chkd/date: VASANTHA/270117; Crtd /date: MANIRAJA/270117; Custom_Duty: 15%; Customs_HS_Code: 85332119; Distributor_name: DIGIKEY; Distributor_part_number: 311-10.0KMCT-ND; Footprint Path: Y:\MIS_DATABASE\Library\ALTIUM_TOOL\PCB_FOOTPRINTS\Altium_Footprint_Lib.PcbLib; Height: 0.26MM; Library Path: Y:\MIS_DATABASE\Library\ALTIUM_TOOL\SCHEMATICS_PARTS\MS_DISCRETE_Library.schlib; Mfr_name: YAGEO AMERICA; Mfr_part_number: RC0201FR-0710KL; Mistral Part No: 110011040018-R; Package: 0201; Part_type: RESISTORS\FIXED; Project: GOLDEN-I LITE; RoHS: RoHS; Temperature: -55°C+125°C; Tolerance: 1%; Voltage: NA; Wattage: 1/20W; Weight: 0.17mg; Datasheet: Y:\MIS_DATABASE\DATASHEETS\RESISTORS\RCXXXXL-SER_MAR18.PDF
R259 = RESISTOR: RES 866E 1/16W 1% 0402; Chkd/date: RAJESH/230414; Crtd /date: BAVISH/010611; Custom_Duty: 15%; Customs_HS_Code: 85332119; Distributor_name: DIGIKEY; Distributor_part_number: 541-866LCT-ND; Footprint Path: Y:\MIS_DATABASE\Library\ALTIUM_TOOL\PCB_FOOTPRINTS\Altium_Footprint_Lib.PcbLib; Height: 0.40MM; Library Path: Y:\MIS_DATABASE\Library\ALTIUM_TOOL\SCHEMATICS_PARTS\MS_DISCRETE_Library.schlib; Mfr_name: VISHAY; Mfr_part_number: CRCW0402866RFKED; Mistral Part No: 110011060007-R; Package: 0402; Part_type: RESISTORS\FIXED; Project: TE_MODULE; RoHS: RoHS; Temperature: -55°C+155°C; Tolerance: 1%; Voltage: NA; Wattage: 1/16W; Weight: 0.65mg; Datasheet: Y:\MIS_DATABASE\DATASHEETS\RESISTORS\CRCW0603.PDF
TP1 TP33 TP34 = TESTPOINT: TESTPOINT 1.0MM DRILL PTH; Chkd/date: MAZHAR/271211; Crtd /date: SHREESHAIL/041005; Distributor_name: NA; Distributor_part_number: NA; Height: NA; Mfr_name: LOCAL; Mistral Part No: 130009030938; Package: THRU-HOLE; Project: HSE; Datasheet: NA
TP32 TP35 TP37 TP51-TP53 TP55 TP56 = TESTPOINT: TESTPOINT CIR 40 SMD; Chkd/date: MAZHAR/190505; Crtd /date: MAZHAR/190505; Distributor_name: NA; Distributor_part_number: NA; Footprint Path: Y:\MIS_DATABASE\Library\ALTIUM_TOOL\PCB_FOOTPRINTS\Altium_Footprint_Lib.PcbLib; Height: NA; Library Path: Y:\MIS_DATABASE\Library\ALTIUM_TOOL\SCHEMATICS_PARTS\MS_DISCRETE_Library.schlib; MECHANICAL 3D STEP FILE: NA; Mfr_name: LOCAL; Mistral Part No: 130009030933; Package: SMD; Project: RAINIER-3; RoHS: NA; Temperature: NA; Tolerance: NA; Voltage: NA; Wattage: NA; Weight: NA; Datasheet: NA
TP38-TP40 = TESTPOINT: TESTPOINT CIR 30 SMD; Chkd/date: SHREESHAIL/171006; Crtd /date: MAZHAR/171006; Custom_Duty: NA; Customs_HS_Code: NA; Distributor_name: NA; Distributor_part_number: NA; Footprint Path: Y:\MIS_DATABASE\Library\ALTIUM_TOOL\PCB_FOOTPRINTS\Altium_Footprint_Lib.PcbLib; Height: NA; Library Path: Y:\MIS_DATABASE\Library\ALTIUM_TOOL\SCHEMATICS_PARTS\MS_DISCRETE_Library.schlib; MECHANICAL 3D STEP FILE: NA; Mfr_name: LOCAL; Mistral Part No: 130009030930; Package: SMD; Project: BT MODULE_CSRBC04; RoHS: NA; Temperature: NA; Tolerance: NA; Voltage: NA; Wattage: NA; Weight: NA; Datasheet: NA
U19 = TPS62827DMQR_VSONHR6: IC 3A 1.8V STEP-DOWN CONVERTER WITH 1% OUTPUT ACCURACY VSON-HR6; Chkd/date: MANIRAJA/101120; Crtd /date: ALVY/101120; Custom_Duty: 15%; Customs_HS_Code: 85423100; Distributor_name: DIGIKEY; Distributor_part_number: 296-TPS6282618DMQTCT-ND; Footprint Path: Y:\MIS_DATABASE\Library\ALTIUM_TOOL\PCB_FOOTPRINTS\Altium_Footprint_Lib.PcbLib; Height: 1.00MM; Library Path: Y:\MIS_DATABASE\Library\ALTIUM_TOOL\SCHEMATICS_PARTS\MS_MISCPOWER_Library.schlib; Mfr_name: TEXAS INSTRUMENTS; Mistral Part No: 142020110012-R; Package: VSON-HR6; Part_type: ICS\POWER\DC-DC CONVERTER; Project: TI_J7ES_EVM_FUSION2_SER_CAP; RoHS: RoHS; Temperature: -40°C+125°C; Tolerance: NA; Voltage: NA; Wattage: NA; Weight: 5mg; Datasheet: Y:\MIS_DATABASE\DATASHEETS\ICS\POWER\TPS6282XX-OCT2020.PDF
U28 = TPS54620_QFN14: IC BUCK SYNCHRONOUS STEP DOWN SWIFT CONVERTER QFN14; Chkd/date: NAVEED/260814; Crtd /date: VASANTHA/250714; Custom_Duty: 15%; Customs_HS_Code: 85423100; Distributor_name: DIGIKEY; Distributor_part_number: 296-28831-1-ND; Height: 1.00MM; Mfr_name: TEXAS INSTRUMENTS; Mistral Part No: 142014070019-R; Package: QFN14; Part_type: ICS\POWER\DC-DC CONVERTER; Project: DC_MIST_RF-TEST CARD; RoHS: RoHS; Temperature: -40°C+150°C; Tolerance: NA; Voltage: NA; Wattage: NA; Weight: NA; Datasheet: Y:\MIS_DATABASE\DATASHEETS\ICS\POWER\TPS54620.PDF
U29-U31 = TPS74801DRCR_SON10: IC 1.5A ADJ LDO LINER REGULATOR WITH PROG SOFT-START VSON10; Chkd/date: MANIRAJA/220818; Crtd /date: ALVY/220818; Custom_Duty: 15%; Customs_HS_Code: 85423100; Distributor_name: DIGIKEY; Distributor_part_number: 296-27887-1-ND; Footprint Path: Y:\MIS_DATABASE\Library\ALTIUM_TOOL\PCB_FOOTPRINTS\Altium_Footprint_Lib.PcbLib; Height: 1.00MM; Library Path: Y:\MIS_DATABASE\Library\ALTIUM_TOOL\SCHEMATICS_PARTS\MS_MISCPOWER_Library.schlib; Mfr_name: TEXAS INSTRUMENTS; Mistral Part No: 142018080014-R; Package: VSON10; Part_type: ICS\POWER\VOLTAGE REGULATOR; Project: TI_J7ES_EVM_FUSION2_SER_CAP; RoHS: RoHS; Temperature: -40°C+105°C; Tolerance: NA; Voltage: NA; Wattage: NA; Weight: 39.3mg; Datasheet: Y:\MIS_DATABASE\DATASHEETS\ICS\POWER\TPS74801XX-Q1.PDF
U33 = TPS54318RTE_QFN16: IC 2.95-6V 6A SYNC STEP DOWN SWIFT CONVERTER WQFN16; Chkd/date: MANIRAJA/030619; Crtd /date: ALVY/310519; Custom_Duty: 15%; Customs_HS_Code: 85423100; Distributor_name: DIGIKEY; Distributor_part_number: 296-28148-1-ND; Height: 0.80MM; Mfr_name: TEXAS INSTRUMENTS; Mistral Part No: 142019060003-R; Package: WQFN16; Part_type: ICS\POWER\CONVERTER; Project: MYTHIC_FORMFACTOR_BRD; RoHS: RoHS; Temperature: -40°C+150°C; Tolerance: NA; Voltage: NA; Wattage: NA; Weight: 40mg; Datasheet: Y:\MIS_DATABASE\DATASHEETS\ICS\POWER\TPS54618-SER.PDF
U35 = LM25085A_WSON8: IC 42V CONSTANT ON-TIME PFET BUCK SWITCHING CONTROLLER WITH 0.9V REFERENCE WSON8; Chkd/date: PRAVEEN/230822; Crtd /date: TAMILARASU/230822; Custom_Duty: 15%; Customs_HS_Code: 85423100; Distributor_name: DIGIKEY; Distributor_part_number: 296-LM25085ASD/NOPBCT-ND; Footprint Path: Y:\MIS_DATABASE\Library\ALTIUM_TOOL\PCB_FOOTPRINTS\Altium_Footprint_Lib.PcbLib; Height: 0.80MM; Library Path: Y:\MIS_DATABASE\Library\ALTIUM_TOOL\SCHEMATICS_PARTS\MS_MISCPOWER_Library.schlib; Mfr_name: TEXAS INSTRUMENTS; Mfr_part_number: LM25085ASD/NOPB; Mistral Part No: 142022080036-R; Package: WSON8; Part_type: ICS\POWER\SWITCHING REGULATOR; Project: J7ES_EVM_FUSION2_BRD; RoHS: RoHS; Temperature: -40°C+125°C; Tolerance: NA; Voltage: NA; Wattage: NA; Weight: NA; Datasheet: Y:\MIS_DATABASE\DATASHEETS\ICS\POWER\LM25085A.PDF
U36 = MOSFET_SI7123DN: IC MOSFET P-CHANNEL 30V PPAK SO-8; Chkd/date: PRAVEEN/230822; Crtd /date: TAMILARASU/230822; Custom_Duty: 15%; Customs_HS_Code: 85423100; Distributor_name: DIGIKEY; Distributor_part_number: SI7149DP-T1-GE3CT-ND; Footprint Path: Y:\MIS_DATABASE\Library\ALTIUM_TOOL\PCB_FOOTPRINTS\Altium_Footprint_Lib.PcbLib; Height: 1.12MM; Library Path: Y:\MIS_DATABASE\Library\ALTIUM_TOOL\SCHEMATICS_PARTS\MS_MOSFET_Library.schlib; Mfr_name: VISHAY; Mistral Part No: 142022080035-R; Package: PPAK SO-8; Part_type: ICS\POWER\MOSFET; Project: J7ES_EVM_FUSION2_BRD; RoHS: RoHS; Temperature: -55°C+150°C; Tolerance: NA; Voltage: 30V; Wattage: NA; Weight: NA; Datasheet: Y:\MIS_DATABASE\DATASHEETS\DISCRETES\TRANSISTORS_FETS\SI7149DP.PDF

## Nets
DGND: C235.2 C236.2 C335.2 C341.2 C344.2 C345.2 C347.2 C348.2 C350.2 C351.2 C352.1 C353.2 C354.2 C355.2 C356.2 C357.2 C358.2 C359.2 C360.2 C361.2 C362.2 C363.2 C364.2 C365.2 C485.2 C491.2 C492.2 C493.2 C495.2 C496.2 C500.2 C501.2 C502.2 C507.2 C508.2 C509.2 C510.2 C511.2 C512.2 C513.2 C514.2 C515.2 C516.2 C517.2 C518.2 C519.2 C521.2 C524.1 C525.2 C527.1 C528.2 C529.2 D2.2(ANODE) D3.1(A1) D3.2(A2) J19.1 R193.2 R198.2 R207.2 R210.2 R213.2 R239.2 R241.2 R254.2 R259.2 U19.4(GND) U28.2(GND1) U28.3(GND2) U28.15(PAD) U29.6(GND) U29.11(PAD) U30.6(GND) U30.11(PAD) U31.6(GND) U31.11(PAD) U33.3(GND1) U33.4(GND2) U33.5(AGND) U33.17(POWER_PAD) U35.4(GND) U35.9(EP) ; also on sheet 4 5 6 7 8 9 10 13 14 15 16
VCC_1V1: C495.1 C496.1 L28.2 R243.1 TP33.1(TP) ; also on sheet 4 5 6
VCC_1V1_CBOOT: C484.1 U33.13(BOOT)
VCC_1V1_COMP: C502.1 R244.1 U33.7(COMP)
VCC_1V1_EN: R197.2 U33.15(EN)
VCC_1V1_FB: R239.1 R243.2 U33.6(VSENSE)
VCC_1V1_PG: R245.1 U33.14(PWRGD)
VCC_1V1_SW: C484.2 L28.1 U33.10(PH1) U33.11(PH2) U33.12(PH3)
VCC_1V8: C235.1 C236.1 C508.1 L29.2 TP1.1(TP) U19.3(FB) ; also on sheet 4 5 6 7 10
VCC_1V8_EN: R145.1 U19.1(EN)
VCC_1V8_SW: L29.1 U19.5(SW)
VCC_3V3: C509.1 C510.1 U19.6(VIN) ; also on sheet 4 6 10
VCC_12V: C341.1 C344.1 C347.1 C526.1 C527.2 C528.1 L30.2 R253.1 R258.1 TP56.1(TP) U28.4(PVIN1) U28.5(PVIN2) U28.6(VIN) ; also on sheet 8 9 13 14 15 16
VCC_12V/20V_HDR: C352.2 C353.1 D2.1(CATHODE) F1.1 J19.2 TP35.1(TP)
VCC_12V_EXP_CONN: F2.1 ; also on sheet 4 6
VCC_CSI_IO: R145.2 R197.1 R206.1 R209.1 R212.1 ; also on sheet 4 5 6 10
VDD_1V1_HUB1: C356.1 C516.1 R208.1 TP51.1(TP) U29.9(OUT1) U29.10(OUT2) ; also on sheet 4
VDD_1V1_HUB1_EN: R206.2 U29.5(EN)
VDD_1V1_HUB1_FB: R207.1 R208.2 U29.8(FB)
VDD_1V1_HUB1_PG: TP38.1(TP) U29.3(PG)
VDD_1V1_HUB1_SS: C363.1 U29.7(SS)
VDD_1V1_HUB2: C359.1 C513.1 R211.1 TP52.1(TP) U30.9(OUT1) U30.10(OUT2) ; also on sheet 5
VDD_1V1_HUB2_EN: R209.2 U30.5(EN)
VDD_1V1_HUB2_FB: R210.1 R211.2 U30.8(FB)
VDD_1V1_HUB2_PG: TP39.1(TP) U30.3(PG)
VDD_1V1_HUB2_SS: C364.1 U30.7(SS)
VDD_1V1_HUB3: C362.1 C519.1 R214.1 TP53.1(TP) U31.9(OUT1) U31.10(OUT2) ; also on sheet 6
VDD_1V1_HUB3_EN: R212.2 U31.5(EN)
VDD_1V1_HUB3_FB: R213.1 R214.2 U31.8(FB)
VDD_1V1_HUB3_PG: TP40.1(TP) U31.3(PG)
VDD_1V1_HUB3_SS: C365.1 U31.7(SS)
LM25085A_FB: C526.2 R258.2 R259.1 U35.3(FB)
LM25085A_ISEN: R255.2 U35.5(ISEN) U36.5(D1)
VCC_1V1_RT/CLK: R241.1 U33.8(RT/CLK)
VCC_1V1_SS/TR: C500.1 U33.9(SS/TR)
VMAIN: C351.1 C521.1 C522.2 C523.1 C524.2 C525.1 C529.1 D1.3(K) F1.2 R255.1 R256.2 R257.1 TP34.1(TP) U35.8(VIN)
